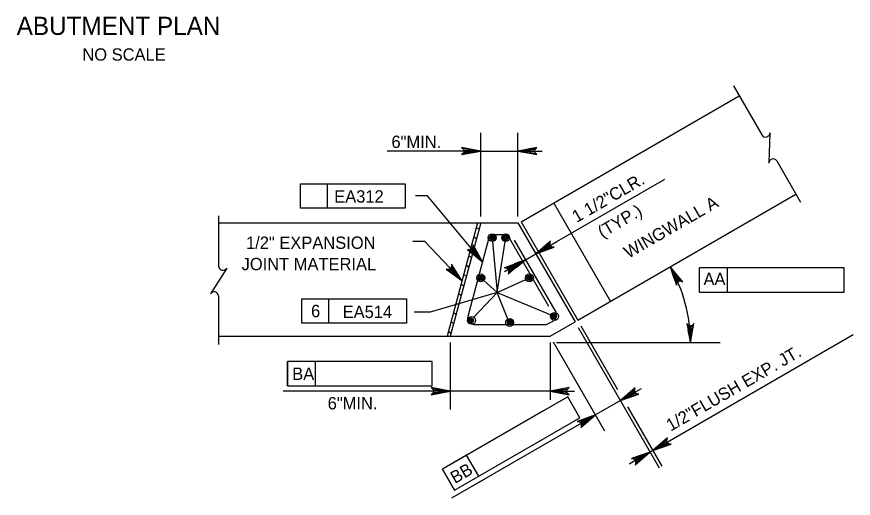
# Model space of a CAD drawing. Extents: x 638255 to 640306, y 296059 to 298435.
# Drawn here: x 638699.3 to 638903, y 296924.9 to 297042 of the extents above; entities that cross this region are included whole.
import ezdxf

# ---------------------------------------------------------------- set-up
doc = ezdxf.new("R2010")
doc.units = 0
for name, color, linetype in [('Level 10', 7, 'Continuous'), ('Level 3', 7, 'Continuous'), ('Level 4', 7, 'Continuous'), ('Level 5', 7, 'Continuous')]:
    doc.layers.add(name, color=color, linetype=linetype)

msp = doc.modelspace()

# ---------------------------------------------------------------- linework, layer by layer
at = {"layer": 'Level 10'}
for p, q in [((638822.07, 296992.08), (638875.2, 297022.76)), ((638835.89, 296968.16), (638889.01, 296998.83)), ((638830.05, 296996.69), (638843.87, 296972.76)), ((638748.44, 296991.9), (638821.29, 296991.9)), ((638811.46, 296991.9), (638804.05, 296964.27)), ((638812.25, 296991.9), (638804.85, 296964.27)), ((638811.15, 296990.77), (638811.84, 296990.38)), ((638821.29, 296991.9), (638835.22, 296967.77)), ((638822.07, 296992.08), (638835.89, 296968.16)), ((638810.54, 296988.47), (638811.23, 296988.07)), ((638809.92, 296986.17), (638810.61, 296985.77)), ((638809.31, 296983.87), (638809.99, 296983.47)), ((638808.69, 296981.57), (638809.38, 296981.17)), ((638808.07, 296979.26), (638808.76, 296978.86)), ((638807.45, 296976.96), (638808.14, 296976.56)), ((638806.84, 296974.66), (638807.53, 296974.26)), ((638806.22, 296972.36), (638806.91, 296971.96)), ((638805.6, 296970.05), (638806.29, 296969.65)), ((638804.99, 296967.75), (638805.68, 296967.35)), ((638829.16, 296964.27), (638835.22, 296967.77)), ((638748.44, 296964.27), (638829.16, 296964.27)), ((638804.37, 296965.45), (638805.06, 296965.05))]:
    msp.add_line(p, q, dxfattribs=at)
at = {"layer": 'Level 3'}
for p, q in [((638812.25, 296993.43), (638812.25, 297013.76)), ((638821.29, 296993.43), (638821.29, 297013.76)), ((638812.25, 297009.34), (638789.48, 297009.34)), ((638812.25, 297009.34), (638821.29, 297009.34)), ((638821.29, 297009.34), (638827.19, 297009.34)), ((638830.76, 296987.29), (638857.06, 297002.47)), ((638768.38, 297001.36), (638793.87, 297001.36)), ((638768.38, 296995.46), (638768.38, 297001.36)), ((638774.96, 296995.46), (638774.96, 297001.36)), ((638793.87, 297001.36), (638793.87, 296995.46)), ((638799.33, 296998.4), (638796.38, 296998.4)), ((638812.68, 296982.38), (638799.33, 296998.4)), ((638793.87, 296995.46), (638768.38, 296995.46)), ((638798.67, 296987.35), (638795.72, 296987.35)), ((638807.69, 296977.86), (638798.67, 296987.35)), ((638815.14, 296987.3), (638816.27, 296974.88)), ((638816.27, 296974.88), (638818.18, 296987.3)), ((638825.66, 296984.34), (638830.76, 296987.29)), ((638823.16, 296982.9), (638825.66, 296984.34)), ((638822.5, 296982.52), (638818.06, 296979.96)), ((638823.4, 296982.49), (638825.37, 296979.08)), ((638825.9, 296983.93), (638827.87, 296980.52)), ((638865.49, 296975.02), (638865.49, 296980.92)), ((638893.89, 296980.92), (638865.49, 296980.92)), ((638872.32, 296980.92), (638865.49, 296980.92)), ((638872.32, 296975.02), (638872.32, 296980.92)), ((638900.73, 296980.92), (638893.89, 296980.92)), ((638900.73, 296975.02), (638900.73, 296980.92)), ((638816.27, 296974.88), (638823.24, 296978.08)), ((638812.98, 296977.84), (638816.27, 296974.88)), ((638816.27, 296974.88), (638799.98, 296970.13)), ((638810.57, 296968.93), (638816.27, 296974.88)), ((638818.82, 296968.46), (638816.27, 296974.88)), ((638816.27, 296974.88), (638829.35, 296969.47)), ((638865.49, 296975.02), (638900.73, 296975.02)), ((638768.69, 296973.34), (638794.18, 296973.34)), ((638768.69, 296967.44), (638768.69, 296973.34)), ((638775.27, 296967.44), (638775.27, 296973.34)), ((638794.18, 296973.34), (638794.18, 296967.44)), ((638799.98, 296970.13), (638796.04, 296970.13)), ((638794.18, 296967.44), (638768.69, 296967.44)), ((638835.99, 296966.44), (638855.67, 296932.26)), ((638836.66, 296966.83), (638845.57, 296951.34)), ((638859.23, 296939.42), (638902.97, 296964.67)), ((638804.85, 296962.73), (638804.85, 296946.48)), ((638829.16, 296962.73), (638829.16, 296948.78)), ((638829.92, 296962.94), (638842.42, 296941.3)), ((638830.69, 296962.73), (638870.52, 296962.73)), ((638765.22, 296958.12), (638765.22, 296952.23)), ((638793.62, 296958.12), (638765.22, 296958.12)), ((638765.22, 296952.23), (638765.22, 296958.12)), ((638772.05, 296958.12), (638765.22, 296958.12)), ((638772.05, 296952.23), (638772.05, 296958.12)), ((638800.45, 296958.12), (638793.62, 296958.12)), ((638800.45, 296952.23), (638800.45, 296958.12)), ((638765.22, 296952.23), (638800.45, 296952.23)), ((638848.83, 296950.1), (638851.38, 296951.57)), ((638798.96, 296950.9), (638764.16, 296950.9)), ((638773.5, 296950.9), (638770.56, 296950.9)), ((638801.9, 296950.9), (638798.96, 296950.9)), ((638829.16, 296950.9), (638804.85, 296950.9)), ((638833.43, 296949.51), (638827.51, 296946.1)), ((638832.1, 296950.9), (638835.05, 296950.9)), ((638836.38, 296944.41), (638833.43, 296949.51)), ((638846.28, 296948.63), (638840.21, 296945.12)), ((638827.51, 296946.1), (638802.91, 296931.9)), ((638847.99, 296947.14), (638856.34, 296932.65)), ((638805.86, 296926.79), (638836.38, 296944.41)), ((638837.66, 296943.65), (638835.11, 296942.18)), ((638835.11, 296942.18), (638805.11, 296924.86)), ((638856.68, 296937.95), (638859.23, 296939.42)), ((638808.83, 296935.31), (638802.91, 296931.9)), ((638811.78, 296930.21), (638808.83, 296935.31)), ((638853.46, 296936.09), (638854.12, 296936.47)), ((638850.91, 296934.62), (638848.36, 296933.14)), ((638802.91, 296931.9), (638805.86, 296926.79)), ((638805.86, 296926.79), (638802.91, 296931.9)), ((638813.06, 296929.45), (638810.51, 296927.98))]:
    msp.add_line(p, q, dxfattribs=at)
for points in [[(638812.25, 297009.34), (638807.6, 297010.21), (638807.96, 297009.96), (638808.14, 297009.65), (638808.2, 297009.34), (638808.14, 297009.03), (638807.96, 297008.71), (638807.6, 297008.47), (638812.25, 297009.34), (638807.96, 297008.71), (638808.14, 297009.03), (638812.25, 297009.34), (638808.2, 297009.34), (638808.14, 297009.65), (638812.25, 297009.34), (638807.96, 297009.96)], [(638821.29, 297009.34), (638825.95, 297008.47), (638825.59, 297008.71), (638825.4, 297009.03), (638825.35, 297009.34), (638825.4, 297009.65), (638825.59, 297009.96), (638825.95, 297010.21), (638821.29, 297009.34), (638825.59, 297009.96), (638825.4, 297009.65), (638821.29, 297009.34), (638825.35, 297009.34), (638825.4, 297009.03), (638821.29, 297009.34), (638825.59, 297008.71)], [(638812.68, 296982.38), (638810.38, 296986.51), (638810.41, 296986.08), (638810.29, 296985.73), (638810.09, 296985.5), (638809.81, 296985.34), (638809.45, 296985.28), (638809.03, 296985.39), (638812.68, 296982.38), (638809.45, 296985.28), (638809.81, 296985.34), (638812.68, 296982.38), (638810.09, 296985.5), (638810.29, 296985.73), (638812.68, 296982.38), (638810.41, 296986.08)], [(638825.66, 296984.34), (638830.12, 296985.91), (638829.69, 296985.95), (638829.37, 296986.13), (638829.17, 296986.37), (638829.06, 296986.67), (638829.06, 296987.03), (638829.25, 296987.42), (638825.66, 296984.34), (638829.06, 296987.03), (638829.06, 296986.67), (638825.66, 296984.34), (638829.17, 296986.37), (638829.37, 296986.13), (638825.66, 296984.34), (638829.69, 296985.95)], [(638822.5, 296982.52), (638818.03, 296980.95), (638818.47, 296980.91), (638818.78, 296980.74), (638818.99, 296980.49), (638819.1, 296980.19), (638819.09, 296979.83), (638818.9, 296979.44), (638822.5, 296982.52), (638819.09, 296979.83), (638819.1, 296980.19), (638822.5, 296982.52), (638818.99, 296980.49), (638818.78, 296980.74), (638822.5, 296982.52), (638818.47, 296980.91)], [(638807.69, 296977.86), (638805.12, 296981.83), (638805.19, 296981.4), (638805.09, 296981.05), (638804.9, 296980.79), (638804.64, 296980.62), (638804.28, 296980.54), (638803.86, 296980.63), (638807.69, 296977.86), (638804.28, 296980.54), (638804.64, 296980.62), (638807.69, 296977.86), (638804.9, 296980.79), (638805.09, 296981.05), (638807.69, 296977.86), (638805.19, 296981.4)], [(638858.39, 296981.15), (638859.95, 296976.68), (638859.99, 296977.11), (638860.17, 296977.43), (638860.41, 296977.63), (638860.71, 296977.74), (638861.07, 296977.73), (638861.46, 296977.55), (638858.39, 296981.15), (638861.07, 296977.73), (638860.71, 296977.74), (638858.39, 296981.15), (638860.41, 296977.63), (638860.17, 296977.43), (638858.39, 296981.15), (638859.99, 296977.11)], [(638863.3, 296962.73), (638864.18, 296967.39), (638863.93, 296967.03), (638863.62, 296966.84), (638863.3, 296966.79), (638862.99, 296966.84), (638862.68, 296967.03), (638862.43, 296967.39), (638863.3, 296962.73), (638862.68, 296967.03), (638862.99, 296966.84), (638863.3, 296962.73), (638863.3, 296966.79), (638863.62, 296966.84), (638863.3, 296962.73), (638863.93, 296967.03)], [(638804.85, 296950.9), (638800.2, 296951.77), (638800.55, 296951.52), (638800.74, 296951.21), (638800.79, 296950.9), (638800.74, 296950.59), (638800.55, 296950.27), (638800.2, 296950.03), (638804.85, 296950.9), (638800.55, 296950.27), (638800.74, 296950.59), (638804.85, 296950.9), (638800.79, 296950.9), (638800.74, 296951.21), (638804.85, 296950.9), (638800.55, 296951.52)], [(638829.16, 296950.9), (638833.81, 296950.03), (638833.45, 296950.27), (638833.26, 296950.59), (638833.21, 296950.9), (638833.26, 296951.21), (638833.45, 296951.52), (638833.81, 296951.77), (638829.16, 296950.9), (638833.45, 296951.52), (638833.26, 296951.21), (638829.16, 296950.9), (638833.21, 296950.9), (638833.26, 296950.59), (638829.16, 296950.9), (638833.45, 296950.27)], [(638846.25, 296948.62), (638850.72, 296950.19), (638850.28, 296950.22), (638849.97, 296950.4), (638849.77, 296950.65), (638849.66, 296950.94), (638849.66, 296951.3), (638849.85, 296951.7), (638846.25, 296948.62), (638849.66, 296951.3), (638849.66, 296950.94), (638846.25, 296948.62), (638849.77, 296950.65), (638849.97, 296950.4), (638846.25, 296948.62), (638850.28, 296950.22)], [(638840.21, 296945.12), (638835.75, 296943.56), (638836.18, 296943.52), (638836.49, 296943.34), (638836.7, 296943.1), (638836.81, 296942.8), (638836.8, 296942.44), (638836.62, 296942.04), (638840.21, 296945.12), (638836.8, 296942.44), (638836.81, 296942.8), (638840.21, 296945.12), (638836.7, 296943.1), (638836.49, 296943.34), (638840.21, 296945.12), (638836.18, 296943.52)], [(638854.13, 296936.48), (638858.6, 296938.05), (638858.16, 296938.08), (638857.84, 296938.26), (638857.64, 296938.5), (638857.53, 296938.8), (638857.54, 296939.16), (638857.72, 296939.56), (638854.13, 296936.48), (638857.54, 296939.16), (638857.53, 296938.8), (638854.13, 296936.48), (638857.64, 296938.5), (638857.84, 296938.26), (638854.13, 296936.48), (638858.16, 296938.08)], [(638853.45, 296936.08), (638848.98, 296934.52), (638849.42, 296934.48), (638849.74, 296934.3), (638849.94, 296934.06), (638850.05, 296933.76), (638850.04, 296933.4), (638849.86, 296933), (638853.45, 296936.08), (638850.04, 296933.4), (638850.05, 296933.76), (638853.45, 296936.08), (638849.94, 296934.06), (638849.74, 296934.3), (638853.45, 296936.08), (638849.42, 296934.48)]]:
    msp.add_lwpolyline(points, dxfattribs=at)
for points in [[(638809.31, 297009.83), (638809.31, 297008.85), (638812.25, 297009.34)], [(638824.24, 297009.83), (638824.24, 297008.85), (638821.29, 297009.34)], [(638827.96, 296986.24), (638828.45, 296985.39), (638825.66, 296984.34)], [(638811.17, 296984.96), (638810.42, 296984.33), (638812.68, 296982.38)], [(638820.37, 296981.86), (638820.86, 296981.01), (638823.16, 296982.9)], [(638806.02, 296980.33), (638805.31, 296979.65), (638807.69, 296977.86)], [(638859.29, 296978.37), (638860.16, 296978.82), (638858.35, 296981.2)], [(638863.68, 296965.7), (638862.7, 296965.66), (638863.3, 296962.73)], [(638801.9, 296951.39), (638801.9, 296950.41), (638804.85, 296950.9)], [(638832.1, 296951.39), (638832.1, 296950.41), (638829.16, 296950.9)], [(638848.58, 296950.53), (638849.07, 296949.68), (638846.28, 296948.63)], [(638837.41, 296944.08), (638837.9, 296943.23), (638840.21, 296945.12)], [(638856.43, 296938.37), (638856.92, 296937.52), (638854.12, 296936.47)], [(638850.66, 296935.04), (638851.15, 296934.19), (638853.46, 296936.09)]]:
    msp.add_lwpolyline(points, close=True, dxfattribs=at)
for centre in [(638815.05, 296988.25), (638818.33, 296988.25), (638812.27, 296978.48), (638824.12, 296978.48), (638830.24, 296969.11), (638810.03, 296968.14), (638819.29, 296967.62)]:
    msp.add_circle(centre, 0.96, dxfattribs=at)
msp.add_arc((638826.37, 296962.74), 36.94, 0, 29.8962, dxfattribs=at)
at = {"layer": 'Level 4'}
for p, q in [((638873.77, 297025.23), (638880.68, 297013.26)), ((638882.67, 297013.79), (638882.39, 297006.38)), ((638884.32, 297006.96), (638890.15, 296996.86)), ((638748.44, 296993.54), (638748.44, 296983.19)), ((638748.44, 296983.19), (638748.44, 296981.38)), ((638750.42, 296980.84), (638746.48, 296974.57)), ((638748.44, 296974.11), (638748.44, 296962.26))]:
    msp.add_line(p, q, dxfattribs=at)
for centre, start, end in [((638881.61, 297013.79), 210, 0), ((638883.45, 297006.35), 35.3286, 177.8672), ((638749.5, 296981.38), 180, 330), ((638747.38, 296974.01), 5.3286, 147.8672)]:
    msp.add_arc(centre, 1.06, start, end, dxfattribs=at)
at = {"layer": 'Level 5'}
for p, q in [((638815.64, 296989.02), (638817.86, 296989.02)), ((638819.19, 296988.25), (638828.78, 296971.63)), ((638814.16, 296987.88), (638809.12, 296969.08)), ((638820.43, 296987.63), (638830.52, 296970.16)), ((638828.74, 296967.35), (638829.96, 296968.06)), ((638810.6, 296967.15), (638827.97, 296967.15))]:
    msp.add_line(p, q, dxfattribs=at)
for centre, radius in [((638815.09, 296988.23), 0.624), ((638815.09, 296988.23), 0.468), ((638815.09, 296988.23), 0.312), ((638815.09, 296988.23), 0.156), ((638818.27, 296988.25), 0.624), ((638818.27, 296988.25), 0.468), ((638818.27, 296988.25), 0.312), ((638818.27, 296988.25), 0.156), ((638812.32, 296978.46), 0.624), ((638812.32, 296978.46), 0.468), ((638812.32, 296978.46), 0.312), ((638812.32, 296978.46), 0.156), ((638824.12, 296978.48), 0.624), ((638824.12, 296978.48), 0.468), ((638824.12, 296978.48), 0.312), ((638824.12, 296978.48), 0.156), ((638809.87, 296968.13), 0.624), ((638809.87, 296968.13), 0.468), ((638809.87, 296968.13), 0.312), ((638809.87, 296968.13), 0.156), ((638819.38, 296967.72), 0.624), ((638819.38, 296967.72), 0.468), ((638819.38, 296967.72), 0.312), ((638819.38, 296967.72), 0.156), ((638830.09, 296969.19), 0.624), ((638830.09, 296969.19), 0.468), ((638830.09, 296969.19), 0.312), ((638830.09, 296969.19), 0.156)]:
    msp.add_circle(centre, radius, dxfattribs=at)
for centre, start, end in [((638815.64, 296987.49), 90, 165), ((638817.86, 296987.49), 30, 90), ((638829.2, 296969.39), 300, 30), ((638810.6, 296968.68), 165, 270), ((638827.97, 296968.68), 270, 300)]:
    msp.add_arc(centre, 1.53, start, end, dxfattribs=at)

# ---------------------------------------------------------------- texts
at = {"layer": 'Level 3'}
for s, height, p in [('ABUTMENT PLAN', 4.4207, (638699.27, 297037.58)), ('NO SCALE', 3, (638715.26, 297031.32)), ('6"MIN.', 3, (638790.52, 297010.08)), ('EA312', 3, (638776.59, 296996.79)), ('1/2" EXPANSION', 3.0001, (638755.11, 296985.53)), ('JOINT MATERIAL', 3.0001, (638754.03, 296980.34)), ('AA', 3, (638866.5, 296976.71)), ('6', 3, (638770.94, 296968.92)), ('EA514', 3, (638778.64, 296968.7)), ('BA', 3, (638766.36, 296953.64)), ('6"MIN.', 3, (638774.99, 296946.48))]:
    msp.add_text(s, height=height, dxfattribs=at).set_placement(p)
for s, height, rotation, p in [('1 1/2"CLR.', 3, 30.0018, (638835.6, 296991.81)), ('WINGWALL A', 3, 30, (638848.22, 296983.11)), ('(TYP.)', 3, 30.0018, (638841.85, 296988.1)), ('1/2"FLUSH EXP. JT.', 3.0001, 30.0031, (638858.51, 296941.05)), ('BB', 3, 30, (638805.97, 296928.31))]:
    msp.add_text(s, height=height, rotation=rotation, dxfattribs=at).set_placement(p)

doc.saveas('drawing.dxf')
